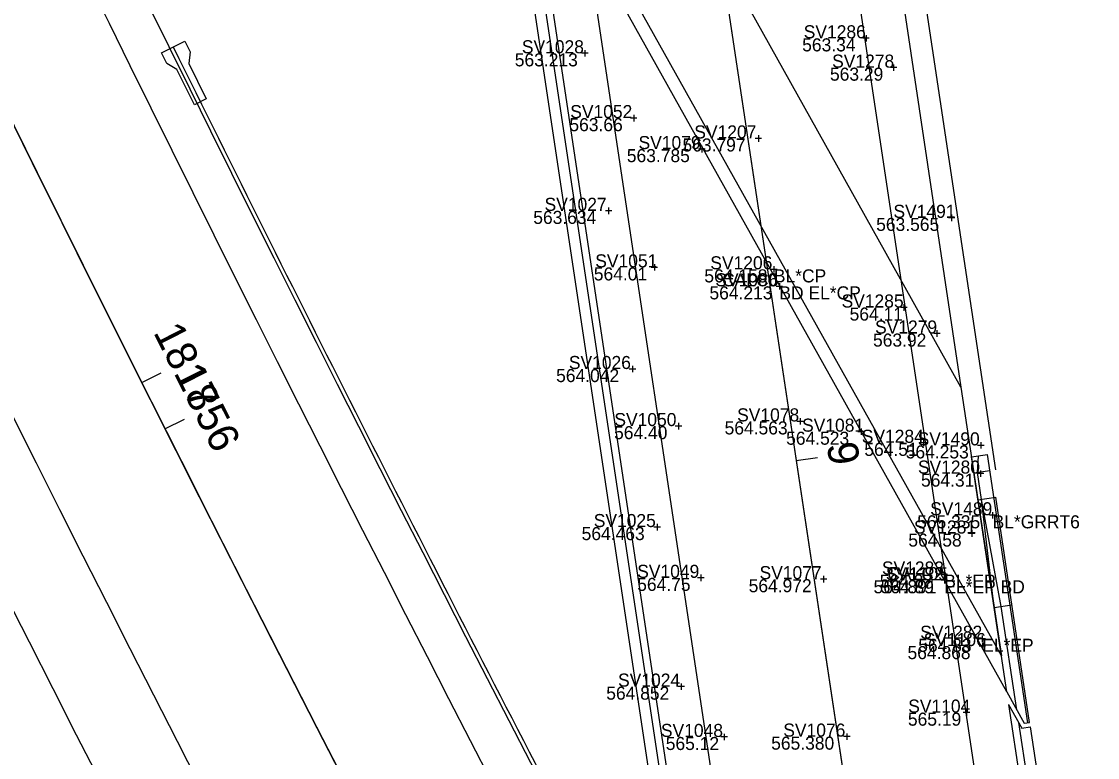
# Model space of a CAD drawing. Extents: x 6334 to 41599, y 9030 to 59113.
# Drawn here: x 21027.9 to 21126.9, y 34484.2 to 34551.9 of the extents above; entities that cross this region are included whole.
import ezdxf

# ---------------------------------------------------------------- set-up
doc = ezdxf.new("R2010")
doc.units = 0
for name, color, linetype in [('BR_P_Sub_Backwall', 7, 'Continuous'), ('BR_P_Sub_Hidden', 7, 'Continuous'), ('BR_X_Gen_Approach_Slab', 7, 'Continuous'), ('BR_X_Slab_Centerline', 7, 'Continuous'), ('BR_X_SV_Deck_Top', 7, 'Continuous'), ('BR_X_SV_Deck_Top_Text', 7, 'Continuous'), ('GE_P_CL_20', 7, 'Continuous'), ('GE_X_CL_20', 7, 'Continuous'), ('GE_X_CL_50', 7, 'Continuous'), ('GK_Visualization', 7, 'Continuous'), ('MT_P_Edge_Line', 7, 'Continuous'), ('PM_X_CL_Double_Solid', 7, 'Continuous'), ('PM_X_Lane_Line', 7, 'Continuous'), ('PV_X_EOP', 7, 'Continuous'), ('PV_X_Shoulder', 7, 'Continuous'), ('RD_P_GR_Lt_Replaced', 7, 'Continuous'), ('RD_P_GR_Rt', 7, 'Continuous'), ('RD_X_GR_Lt', 7, 'Continuous'), ('SV_X_Shot_Marker', 7, 'Continuous'), ('SV_X_Text_Comment', 7, 'Continuous'), ('SV_X_Text_Elevation', 7, 'Continuous'), ('SV_X_Text_Name', 7, 'Continuous')]:
    doc.layers.add(name, color=color, linetype=linetype)

msp = doc.modelspace()

# ---------------------------------------------------------------- linework, layer by layer
at = {"layer": 'BR_P_Sub_Backwall'}
msp.add_line((21118.505, 34490.24), (21073.051, 34571.516), dxfattribs=at)
at = {"layer": 'BR_P_Sub_Hidden'}
msp.add_line((21117.8, 34494.938), (21118.01, 34493.537), dxfattribs=at)
at = {"layer": 'BR_X_Gen_Approach_Slab'}
for p, q in [((21114.297, 34518.26), (21070.057, 34597.364)), ((21118.01, 34493.537), (21073.77, 34572.641)), ((21114.297, 34518.26), (21118.01, 34493.537))]:
    msp.add_line(p, q, dxfattribs=at)
at = {"layer": 'BR_X_Slab_Centerline'}
msp.add_line((21088.117, 34584.844), (21156.74, 34127.951), dxfattribs=at)
at = {"layer": 'BR_X_SV_Deck_Top'}
for p, q in [((21072.333, 34570.987), (21124.136, 34226.081)), ((21073.519, 34569.825), (21125.209, 34225.674)), ((21074.441, 34568.177), (21126.13, 34224.026)), ((21115.261, 34511.841), (21116.744, 34512.064)), ((21118.505, 34490.24), (21115.261, 34511.841)), ((21115.814, 34510.408), (21115.92, 34511.94)), ((21120.448, 34487.406), (21116.744, 34512.064)), ((21115.484, 34510.358), (21116.967, 34510.581)), ((21116.185, 34507.935), (21115.814, 34510.408)), ((21115.855, 34507.886), (21117.503, 34508.133)), ((21118, 34498.096), (21116.185, 34507.935)), ((21117.34, 34497.997), (21116.185, 34507.935)), ((21120.613, 34487.431), (21117.503, 34508.133)), ((21117.34, 34497.997), (21118.989, 34498.244)), ((21119.427, 34488.592), (21118, 34498.096)), ((21118.505, 34490.24), (21120.118, 34487.356)), ((21118.681, 34489.073), (21119.895, 34486.901)), ((21118.681, 34489.073), (21170.37, 34144.922)), ((21119.602, 34487.425), (21171.292, 34143.274)), ((21120.118, 34487.356), (21120.613, 34487.431)), ((21119.895, 34486.901), (21120.675, 34487.019)), ((21120.675, 34487.019), (21172.478, 34142.113))]:
    msp.add_line(p, q, dxfattribs=at)
at = {"layer": 'BR_X_SV_Deck_Top_Text'}
for p, q in [((21079.987, 34548.936), (21079.388, 34548.936)), ((21079.688, 34549.236), (21079.688, 34548.636)), ((21090.759, 34540.131), (21090.159, 34540.131)), ((21090.459, 34540.431), (21090.459, 34539.831)), ((21082.179, 34534.453), (21081.579, 34534.453)), ((21081.879, 34534.753), (21081.879, 34534.153)), ((21097.89, 34527.515), (21097.29, 34527.515)), ((21097.59, 34527.815), (21097.59, 34527.215)), ((21084.068, 34520.214), (21084.068, 34519.614)), ((21084.368, 34519.914), (21083.768, 34519.914)), ((21105.416, 34514.154), (21104.816, 34514.154)), ((21105.116, 34514.454), (21105.116, 34513.854)), ((21086.648, 34505.386), (21086.048, 34505.386)), ((21086.348, 34505.686), (21086.348, 34505.086)), ((21113.069, 34500.496), (21112.469, 34500.496)), ((21112.769, 34500.796), (21112.769, 34500.196)), ((21116.565, 34494.447), (21115.965, 34494.447)), ((21116.265, 34494.747), (21116.265, 34494.147)), ((21088.856, 34490.72), (21088.256, 34490.72)), ((21088.556, 34491.02), (21088.556, 34490.42))]:
    msp.add_line(p, q, dxfattribs=at)
at = {"layer": 'GE_P_CL_20'}
msp.add_line((21099.133, 34511.499), (21101.111, 34511.796), dxfattribs=at)
at = {"layer": 'GE_X_CL_20'}
for p, q in [((21038.922, 34518.676), (21040.709, 34519.574)), ((21041.062, 34514.419), (21042.848, 34515.319))]:
    msp.add_line(p, q, dxfattribs=at)
msp.add_arc((24529.938, 36271.897), 3906.53, 186.216667, 209.216667, dxfattribs=at)
at = {"layer": 'GE_X_CL_50'}
msp.add_arc((32581.775, 39251.958), 12277.667, 194.525, 202.7166667, dxfattribs=at)
at = {"layer": 'GK_Visualization'}
msp.add_line((21084.271, 34610.451), (21262.514, 33423.702), dxfattribs=at)
msp.add_line((21084.271, 34610.451), (21262.514, 33423.702), dxfattribs=at)
for centre, radius, start, end in [((32581.775, 39251.958), 12277.667, 194.525, 202.7166667), ((32581.775, 39251.958), 12277.667, 194.525, 202.7166667), ((24529.914, 36271.941), 3906.53, 186.214966, 209.213797), ((24529.914, 36271.941), 3906.53, 186.214966, 209.213797), ((24529.938, 36271.897), 3906.53, 186.216667, 209.216667), ((24529.938, 36271.897), 3906.53, 186.216667, 209.216667)]:
    msp.add_arc(centre, radius, start, end, dxfattribs=at)
at = {"layer": 'MT_P_Edge_Line'}
msp.add_line((21116.151, 34507.93), (21116.185, 34507.935), dxfattribs=at)
at = {"layer": 'PM_X_CL_Double_Solid'}
msp.add_line((21084.271, 34610.451), (21262.514, 33423.702), dxfattribs=at)
at = {"layer": 'PM_X_Lane_Line'}
for start in [186.216667, 191.336069]:
    msp.add_arc((24529.938, 36271.897), 3906.53, start, 209.216667, dxfattribs=at)
at = {"layer": 'PV_X_EOP'}
for p, q in [((21096.138, 34612.234), (21274.381, 33425.485)), ((21072.404, 34608.669), (21250.647, 33421.92))]:
    msp.add_line(p, q, dxfattribs=at)
for centre, radius, start, end in [((24529.938, 36271.897), 3918.53, 191.336069, 209.216667), ((24531.789, 36272.609), 3896.493, 192.870453, 209.21252)]:
    msp.add_arc(centre, radius, start, end, dxfattribs=at)
at = {"layer": 'PV_X_Shoulder'}
for p, q in [((21100.093, 34612.828), (21114.297, 34518.26)), ((21095.89, 34533.089), (21095.89, 34533.089))]:
    msp.add_line(p, q, dxfattribs=at)
for radius, start in [(3926.53, 191.341411), (3890.53, 192.866306)]:
    msp.add_arc((24529.938, 36271.897), radius, start, 209.216667, dxfattribs=at)
at = {"layer": 'RD_P_GR_Lt_Replaced'}
msp.add_arc((24528.367, 36271.332), 3888.53, 206.282233, 207.386681, dxfattribs=at)
at = {"layer": 'RD_P_GR_Rt'}
for p, q in [((21040.734, 34548.981), (21042.903, 34550.053)), ((21042.903, 34550.053), (21043.388, 34549.072)), ((21041.219, 34547.999), (21040.734, 34548.981)), ((21043.388, 34549.072), (21043.246, 34547.995)), ((21042.161, 34547.459), (21041.219, 34547.999)), ((21043.246, 34547.995), (21044.854, 34544.741)), ((21043.769, 34544.204), (21042.161, 34547.459)), ((21044.854, 34544.741), (21043.769, 34544.204))]:
    msp.add_line(p, q, dxfattribs=at)
at = {"layer": 'RD_X_GR_Lt'}
msp.add_line((21102.071, 34613.125), (21117.462, 34510.655), dxfattribs=at)
at = {"layer": 'SV_X_Shot_Marker'}
for p, q in [((21105.864, 34550.313), (21105.264, 34550.313)), ((21105.564, 34550.613), (21105.564, 34550.013)), ((21108.101, 34547.918), (21108.101, 34547.318)), ((21108.401, 34547.618), (21107.801, 34547.618)), ((21084.484, 34542.977), (21083.885, 34542.977)), ((21084.184, 34543.277), (21084.184, 34542.677)), ((21095.957, 34541.11), (21095.357, 34541.11)), ((21095.657, 34541.41), (21095.657, 34540.81)), ((21113.439, 34534.111), (21113.439, 34533.511)), ((21113.739, 34533.811), (21113.139, 34533.811)), ((21086.389, 34529.256), (21085.789, 34529.256)), ((21086.089, 34529.556), (21086.089, 34528.956)), ((21097.381, 34529.077), (21096.781, 34529.077)), ((21097.081, 34529.377), (21097.081, 34528.776)), ((21097.89, 34527.515), (21097.29, 34527.515)), ((21097.59, 34527.815), (21097.59, 34527.215)), ((21109.335, 34525.566), (21108.735, 34525.566)), ((21109.035, 34525.866), (21109.035, 34525.266)), ((21112.389, 34523.176), (21111.789, 34523.176)), ((21112.089, 34523.476), (21112.089, 34522.876)), ((21099.792, 34515.101), (21099.193, 34515.101)), ((21099.493, 34515.401), (21099.493, 34514.801)), ((21088.603, 34514.669), (21088.003, 34514.669)), ((21088.303, 34514.969), (21088.303, 34514.369)), ((21111.163, 34513.131), (21110.563, 34513.131)), ((21110.863, 34513.431), (21110.863, 34512.831)), ((21116.121, 34513.196), (21116.121, 34512.595)), ((21116.421, 34512.895), (21115.821, 34512.895)), ((21116.397, 34510.3), (21115.797, 34510.3)), ((21116.097, 34510.6), (21116.097, 34510)), ((21117.508, 34506.468), (21116.908, 34506.468)), ((21117.208, 34506.768), (21117.208, 34506.168)), ((21115.581, 34504.794), (21114.981, 34504.794)), ((21115.281, 34505.094), (21115.281, 34504.494)), ((21112.758, 34501.322), (21112.758, 34500.722)), ((21090.666, 34500.719), (21090.066, 34500.719)), ((21090.366, 34501.019), (21090.366, 34500.419)), ((21101.959, 34500.596), (21101.359, 34500.596)), ((21101.659, 34500.896), (21101.659, 34500.296)), ((21113.058, 34501.022), (21112.458, 34501.022)), ((21113.069, 34500.496), (21112.469, 34500.496)), ((21112.769, 34500.796), (21112.769, 34500.196)), ((21116.25, 34495.419), (21116.25, 34494.819)), ((21116.55, 34495.119), (21115.95, 34495.119)), ((21114.798, 34488.628), (21114.798, 34488.028)), ((21115.098, 34488.328), (21114.498, 34488.328)), ((21092.51, 34486.392), (21092.51, 34485.792)), ((21103.798, 34486.424), (21103.798, 34485.824)), ((21092.81, 34486.092), (21092.21, 34486.092)), ((21104.098, 34486.124), (21103.498, 34486.124))]:
    msp.add_line(p, q, dxfattribs=at)

# ---------------------------------------------------------------- texts
at = {"layer": 'BR_X_SV_Deck_Top_Text'}
for s, p in [('SV1028', (21073.896, 34548.936)), ('563.213', (21073.244, 34547.736)), ('SV1079', (21084.63, 34540.131)), ('563.785', (21083.552, 34538.931)), ('SV1027', (21075.985, 34534.453)), ('563.634', (21074.944, 34533.253)), ('SV1080', (21091.695, 34527.515)), ('564.213', (21091.156, 34526.315)), ('BD EL*CP', (21097.59, 34526.315)), ('SV1026', (21078.22, 34519.914)), ('564.042', (21077.048, 34518.714)), ('SV1081', (21099.676, 34514.154)), ('564.523', (21098.209, 34512.954)), ('SV1025', (21080.51, 34505.386)), ('564.463', (21079.395, 34504.186)), ('CALC2', (21107.525, 34500.496)), ('564.891', (21106.251, 34499.296)), ('SV1106', (21110.871, 34494.447)), ('564.868', (21109.377, 34493.247)), ('SV1024', (21082.746, 34490.72)), ('564.852', (21081.659, 34489.52))]:
    msp.add_text(s, height=1.2, dxfattribs=at).set_placement(p)
at = {"layer": 'GE_P_CL_20'}
msp.add_text('9', height=2.8, rotation=278.54167, dxfattribs=at).set_placement((21101.943, 34512.991))
at = {"layer": 'GE_X_CL_20'}
for s, rotation, p in [('1817', 296.66623, (21039.956, 34523.301)), ('1856', 296.73607, (21041.867, 34519.49))]:
    msp.add_text(s, height=2.8, rotation=rotation, dxfattribs=at).set_placement(p)
at = {"layer": 'SV_X_Text_Comment'}
for s, p in [('BL*CP', (21097.081, 34527.877)), ('BL*GRRT6', (21117.208, 34505.268)), ('BL*EP', (21112.758, 34499.822)), ('EL*EP BD', (21112.769, 34499.296)), ('EL*EP', (21116.25, 34493.919))]:
    msp.add_text(s, height=1.2, dxfattribs=at).set_placement(p)
at = {"layer": 'SV_X_Text_Elevation'}
for s, p in [('563.34', (21099.687, 34549.113)), ('563.29', (21102.243, 34546.418)), ('563.66', (21078.27, 34541.777)), ('563.797', (21088.675, 34539.91)), ('563.565', (21106.494, 34532.611)), ('564.01', (21080.516, 34528.056)), ('564.158', (21090.685, 34527.877)), ('564.213', (21091.156, 34526.315)), ('564.11', (21104.049, 34524.366)), ('563.92', (21106.203, 34521.976)), ('564.563', (21092.548, 34513.901)), ('564.40', (21082.379, 34513.469)), ('564.51', (21105.404, 34511.931)), ('564.253', (21109.214, 34511.696)), ('564.31', (21110.619, 34509.1)), ('565.335', (21110.264, 34505.268)), ('564.58', (21109.452, 34503.594)), ('564.75', (21084.508, 34499.519)), ('564.972', (21094.762, 34499.396)), ('564.87', (21106.824, 34499.822)), ('564.89', (21106.902, 34499.296)), ('564.83', (21110.364, 34493.919)), ('565.19', (21109.413, 34487.128)), ('565.12', (21087.135, 34484.892)), ('565.380', (21096.835, 34484.924))]:
    msp.add_text(s, height=1.2, dxfattribs=at).set_placement(p)
at = {"layer": 'SV_X_Text_Name'}
for s, p in [('SV1286', (21099.829, 34550.313)), ('SV1278', (21102.442, 34547.618)), ('SV1052', (21078.346, 34542.977)), ('SV1207', (21089.762, 34541.11)), ('SV1491', (21108.084, 34533.811)), ('SV1051', (21080.649, 34529.256)), ('SV1206', (21091.233, 34529.077)), ('CALC6', (21092.318, 34527.515)), ('SV1285', (21103.31, 34525.566)), ('SV1279', (21106.392, 34523.176)), ('SV1078', (21093.701, 34515.101)), ('SV1050', (21082.408, 34514.669)), ('SV1284', (21105.167, 34513.131)), ('SV1490', (21110.311, 34512.895)), ('SV1280', (21110.334, 34510.3)), ('SV1489', (21111.464, 34506.468)), ('SV1281', (21109.974, 34504.794)), ('SV1283', (21107.023, 34501.022)), ('SV1049', (21084.509, 34500.719)), ('SV1077', (21095.764, 34500.596)), ('SV1105', (21107.385, 34500.496)), ('SV1282', (21110.544, 34495.119)), ('SV1104', (21109.442, 34488.328)), ('SV1048', (21086.691, 34486.092)), ('SV1076', (21097.95, 34486.124))]:
    msp.add_text(s, height=1.2, dxfattribs=at).set_placement(p)

doc.saveas('drawing.dxf')
